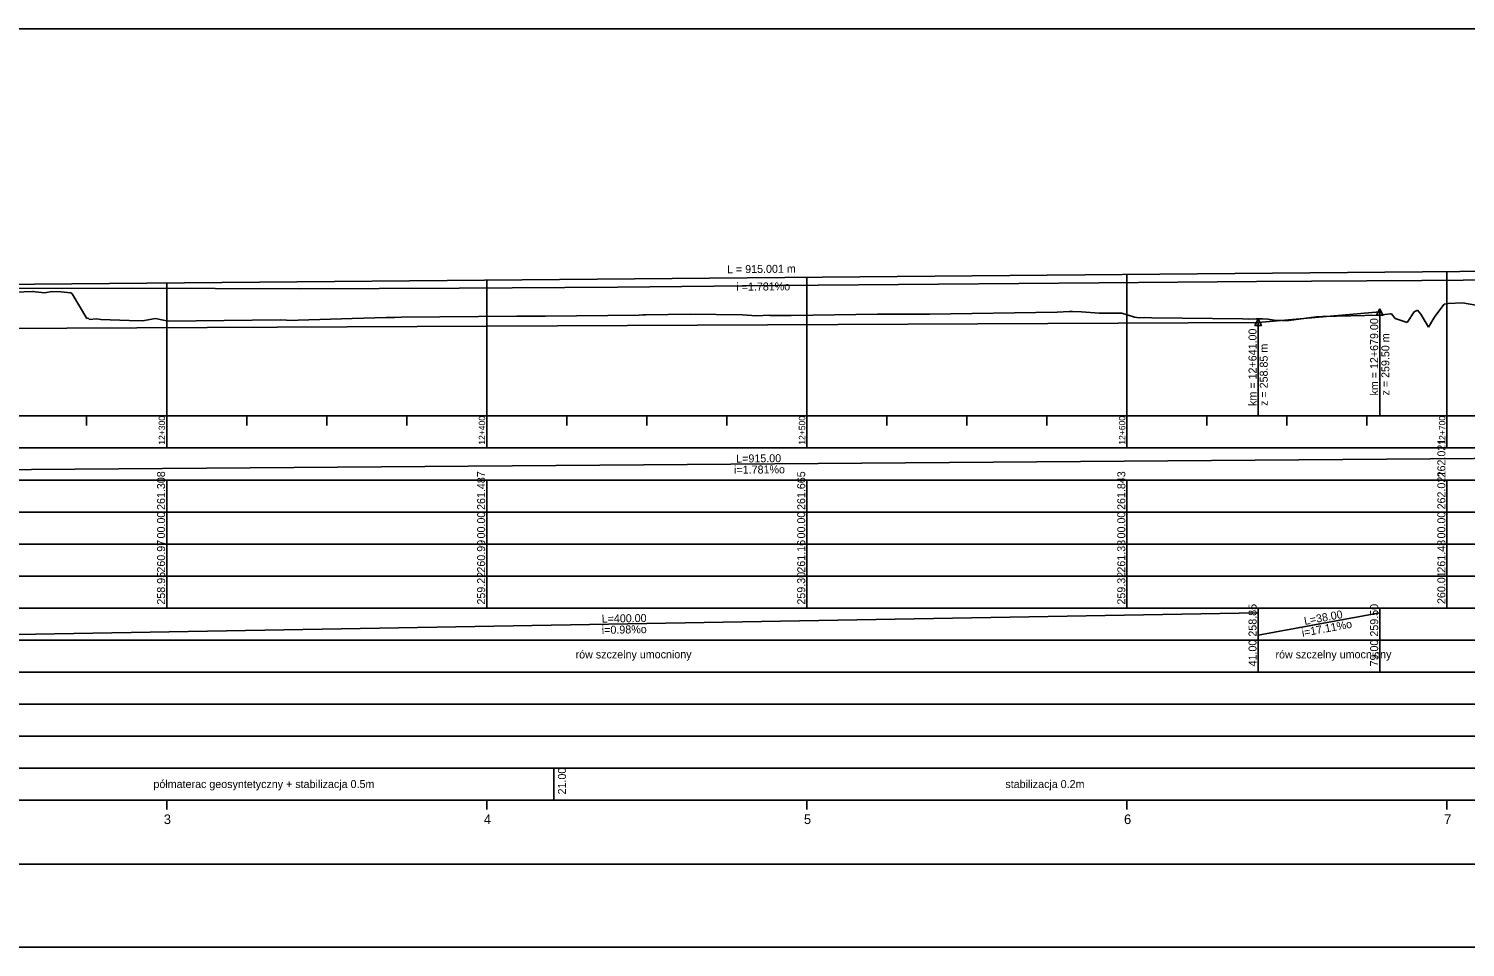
# Model space of a CAD drawing. Extents: x 6445630 to 6518227, y 5499240 to 5511716.
# Drawn here: x 6456888.1 to 6457336.9, y 5506751.3 to 5507038.3 of the extents above; entities that cross this region are included whole.
import ezdxf

# ---------------------------------------------------------------- set-up
doc = ezdxf.new("R2010")
doc.units = 0
for name, color, linetype in [('TOR_PROF-opisy pomocnicze', 7, 'Continuous'), ('TOR_PROF-rowy otwarte', 7, 'Continuous'), ('TOR_PROF-tabelka-geometria T1', 7, 'Continuous'), ('TOR_PROF-tabelka-kilometracja', 7, 'Continuous'), ('TOR_PROF-tabelka-odleglosci T1', 7, 'Continuous'), ('TOR_PROF-tabelka-pochylenia proj T1', 7, 'Continuous'), ('TOR_PROF-tabelka-rodzaj rowu T1', 7, 'Continuous'), ('TOR_PROF-tabelka-rowyT1', 7, 'Continuous'), ('TOR_PROF-tabelka-rurociagi T1', 7, 'Continuous'), ('TOR_PROF-tabelka-rzedne istn T1', 7, 'Continuous'), ('TOR_PROF-tabelka-rzedne proj T1', 7, 'Continuous'), ('TOR_PROF-tabelka-teren istniejacy T1', 7, 'Continuous'), ('TOR_PROF-tabelka-warstwa ochronna T1', 7, 'Continuous'), ('TOR_PROF-tor istniejacy T2', 7, 'Continuous'), ('TOR_PROF-tor projektowany', 7, 'Continuous'), ('TOR_PROF-uklad odniesienia', 7, 'Continuous'), ('TOR_PROF-warstwa ochronna', 7, 'Continuous'), ('TOR_RAMKI-dodatkowe3', 7, 'Continuous'), ('TOR_RAMKI-MASKA WYCIECIA', 7, 'Continuous')]:
    doc.layers.add(name, color=color, linetype=linetype)

msp = doc.modelspace()

# ---------------------------------------------------------------- linework, layer by layer
at = {"layer": 'TOR_PROF-opisy pomocnicze'}
for p, q in [((6457310.21, 5506949.8), (6457310.21, 5506922.8)), ((6457272.21, 5506946.55), (6457272.21, 5506919.55))]:
    msp.add_line(p, q, dxfattribs=at)
for points in [[(6457310.21, 5506950.8), (6457311.21, 5506948.8), (6457309.21, 5506948.8)], [(6457272.21, 5506947.55), (6457273.21, 5506945.55), (6457271.21, 5506945.55)]]:
    msp.add_lwpolyline(points, close=True, dxfattribs=at)
at = {"layer": 'TOR_PROF-rowy otwarte'}
for p, q in [((6457272.21, 5506946.55), (6457310.21, 5506949.8)), ((6456872.21, 5506944.6), (6457272.21, 5506946.55))]:
    msp.add_line(p, q, dxfattribs=at)
for points in [[(6457310.21, 5506949.8), (6457310.21, 5506922.3), (6457310.21, 5506917.3), (6457310.21, 5506917.3)], [(6457272.21, 5506946.55), (6457272.21, 5506922.3), (6457272.21, 5506917.3), (6457272.21, 5506917.3)]]:
    msp.add_lwpolyline(points, dxfattribs=at)
at = {"layer": 'TOR_PROF-tabelka-geometria T1'}
for points in [[(6452735.25, 5506777.3), (6458247.17, 5506777.3), (6458247.17, 5506779.97), (6458376.27, 5506779.97), (6458376.27, 5506777.3), (6458396.27, 5506777.3), (6458396.27, 5506774.64), (6458525.37, 5506774.64), (6458525.37, 5506777.3), (6458723.83, 5506777.3), (6458723.83, 5506777.3), (6458758.83, 5506774.64), (6458758.83, 5506774.64), (6458827.61, 5506774.64), (6458827.61, 5506774.64), (6458862.61, 5506777.3), (6458862.61, 5506777.3), (6458862.61, 5506777.3), (6458862.61, 5506777.3), (6458897.61, 5506779.97), (6458897.61, 5506779.97), (6458966.4, 5506779.97), (6458966.4, 5506779.97), (6459001.4, 5506777.3)], [(6452331.21, 5506777.3), (6459531.21, 5506777.3)]]:
    msp.add_lwpolyline(points, dxfattribs=at)
at = {"layer": 'TOR_PROF-tabelka-kilometracja'}
for points in [[(6456931.21, 5506794.3), (6456931.21, 5506797.3)], [(6457031.21, 5506794.3), (6457031.21, 5506797.3)], [(6457131.21, 5506794.3), (6457131.21, 5506797.3)], [(6457231.21, 5506794.3), (6457231.21, 5506797.3)], [(6457331.21, 5506794.3), (6457331.21, 5506797.3)]]:
    msp.add_lwpolyline(points, dxfattribs=at)
at = {"layer": 'TOR_PROF-tabelka-odleglosci T1'}
msp.add_lwpolyline([(6452331.21, 5506877.3), (6459531.21, 5506877.3), (6459531.21, 5506887.3), (6452331.21, 5506887.3)], close=True, dxfattribs=at)
for points in [[(6456931.21, 5506877.3), (6456931.21, 5506887.3)], [(6457031.21, 5506877.3), (6457031.21, 5506887.3)], [(6457131.21, 5506877.3), (6457131.21, 5506887.3)], [(6457231.21, 5506877.3), (6457231.21, 5506887.3)], [(6457331.21, 5506877.3), (6457331.21, 5506887.3)]]:
    msp.add_lwpolyline(points, dxfattribs=at)
at = {"layer": 'TOR_PROF-tabelka-pochylenia proj T1'}
msp.add_lwpolyline([(6452331.21, 5506897.3), (6459531.21, 5506897.3), (6459531.21, 5506907.3), (6452331.21, 5506907.3)], close=True, dxfattribs=at)
msp.add_lwpolyline([(6456656.74, 5506898.8), (6457571.74, 5506905.8)], dxfattribs=at)
at = {"layer": 'TOR_PROF-tabelka-rodzaj rowu T1'}
for points in [[(6452331.21, 5506837.3), (6459531.21, 5506837.3), (6459531.21, 5506847.3), (6452331.21, 5506847.3)], [(6452331.21, 5506817.3), (6459531.21, 5506817.3), (6459531.21, 5506827.3), (6452331.21, 5506827.3)]]:
    msp.add_lwpolyline(points, close=True, dxfattribs=at)
for points in [[(6457272.21, 5506837.3), (6457272.21, 5506847.3)], [(6457310.21, 5506837.3), (6457310.21, 5506847.3)]]:
    msp.add_lwpolyline(points, dxfattribs=at)
at = {"layer": 'TOR_PROF-tabelka-rowyT1'}
msp.add_lwpolyline([(6452331.21, 5506847.3), (6459531.21, 5506847.3), (6459531.21, 5506857.3), (6452331.21, 5506857.3)], close=True, dxfattribs=at)
for points in [[(6456872.21, 5506848.8), (6457272.21, 5506855.8)], [(6457272.21, 5506847.3), (6457272.21, 5506857.3)], [(6457272.21, 5506848.8), (6457310.21, 5506855.8)], [(6457310.21, 5506847.3), (6457310.21, 5506857.3)]]:
    msp.add_lwpolyline(points, dxfattribs=at)
at = {"layer": 'TOR_PROF-tabelka-rurociagi T1'}
msp.add_lwpolyline([(6452331.21, 5506827.3), (6459531.21, 5506827.3), (6459531.21, 5506837.3), (6452331.21, 5506837.3)], close=True, dxfattribs=at)
at = {"layer": 'TOR_PROF-tabelka-rzedne istn T1'}
msp.add_lwpolyline([(6452331.21, 5506867.3), (6459531.21, 5506867.3), (6459531.21, 5506877.3), (6452331.21, 5506877.3)], close=True, dxfattribs=at)
for points in [[(6456931.21, 5506867.3), (6456931.21, 5506877.3)], [(6457031.21, 5506867.3), (6457031.21, 5506877.3)], [(6457131.21, 5506867.3), (6457131.21, 5506877.3)], [(6457231.21, 5506867.3), (6457231.21, 5506877.3)], [(6457331.21, 5506867.3), (6457331.21, 5506877.3)], [(6456931.21, 5506857.3), (6456931.21, 5506867.3)], [(6456931.21, 5506857.3), (6456931.21, 5506867.3)], [(6456931.21, 5506857.3), (6456931.21, 5506867.3)], [(6457031.21, 5506857.3), (6457031.21, 5506867.3)], [(6457031.21, 5506857.3), (6457031.21, 5506867.3)], [(6457031.21, 5506857.3), (6457031.21, 5506867.3)], [(6457131.21, 5506857.3), (6457131.21, 5506867.3)], [(6457131.21, 5506857.3), (6457131.21, 5506867.3)], [(6457131.21, 5506857.3), (6457131.21, 5506867.3)], [(6457231.21, 5506857.3), (6457231.21, 5506867.3)], [(6457231.21, 5506857.3), (6457231.21, 5506867.3)], [(6457231.21, 5506857.3), (6457231.21, 5506867.3)], [(6457331.21, 5506857.3), (6457331.21, 5506867.3)], [(6457331.21, 5506857.3), (6457331.21, 5506867.3)], [(6457331.21, 5506857.3), (6457331.21, 5506867.3)]]:
    msp.add_lwpolyline(points, dxfattribs=at)
at = {"layer": 'TOR_PROF-tabelka-rzedne proj T1'}
msp.add_lwpolyline([(6452331.21, 5506887.3), (6459531.21, 5506887.3), (6459531.21, 5506897.3), (6452331.21, 5506897.3)], close=True, dxfattribs=at)
for points in [[(6456931.21, 5506887.3), (6456931.21, 5506897.3)], [(6457031.21, 5506887.3), (6457031.21, 5506897.3)], [(6457131.21, 5506887.3), (6457131.21, 5506897.3)], [(6457231.21, 5506887.3), (6457231.21, 5506897.3)], [(6457331.21, 5506887.3), (6457331.21, 5506897.3)]]:
    msp.add_lwpolyline(points, dxfattribs=at)
at = {"layer": 'TOR_PROF-tabelka-teren istniejacy T1'}
msp.add_lwpolyline([(6452331.21, 5506857.3), (6459531.21, 5506857.3), (6459531.21, 5506867.3), (6452331.21, 5506867.3)], close=True, dxfattribs=at)
msp.add_lwpolyline([(6452331.21, 5506857.3), (6459531.21, 5506857.3), (6459531.21, 5506867.3), (6452331.21, 5506867.3)], close=True, dxfattribs=at)
msp.add_lwpolyline([(6452331.21, 5506857.3), (6459531.21, 5506857.3), (6459531.21, 5506867.3), (6452331.21, 5506867.3)], close=True, dxfattribs=at)
at = {"layer": 'TOR_PROF-tabelka-warstwa ochronna T1'}
msp.add_lwpolyline([(6452331.21, 5506807.3), (6459531.21, 5506807.3), (6459531.21, 5506817.3), (6452331.21, 5506817.3)], close=True, dxfattribs=at)
at = {"layer": 'TOR_PROF-tor istniejacy T2'}
msp.add_lwpolyline([(6456273.83, 5506953.65), (6456323.85, 5506953.85), (6456373.37, 5506953.9), (6456420.81, 5506954.3), (6456470.2, 5506954.8), (6456521.75, 5506955.4), (6456572.89, 5506955.4), (6456623.47, 5506955.35), (6456672.67, 5506955.3), (6456723.03, 5506955.55), (6456772.56, 5506955.75), (6456819.97, 5506956.35), (6456866.68, 5506957.1), (6456920.08, 5506957.2), (6456972.6, 5506957.05), (6457022.59, 5506957.2), (6457072.2, 5506957.55), (6457122.23, 5506958.05), (6457172.36, 5506958.45), (6457222.5, 5506958.9), (6457271.74, 5506959.3), (6457323.35, 5506959.65), (6457375.16, 5506960.05)], dxfattribs=at)
at = {"layer": 'TOR_PROF-tor projektowany'}
msp.add_line((6456656.74, 5506956.4), (6457571.74, 5506964.55), dxfattribs=at)
msp.add_line((6456656.74, 5506956.4), (6457571.74, 5506964.55), dxfattribs=at)
for points in [[(6457231.21, 5506961.52), (6457231.21, 5506922.3), (6457231.21, 5506917.3), (6457231.21, 5506917.3)], [(6457231.21, 5506961.52), (6457231.21, 5506922.3), (6457231.21, 5506917.3), (6457231.21, 5506917.3)], [(6457331.21, 5506962.41), (6457331.21, 5506922.3), (6457331.21, 5506917.3), (6457331.21, 5506917.3)], [(6457331.21, 5506962.41), (6457331.21, 5506922.3), (6457331.21, 5506917.3), (6457331.21, 5506917.3)], [(6457331.21, 5506962.41), (6457331.21, 5506922.3), (6457331.21, 5506917.3), (6457331.21, 5506917.3)], [(6456931.21, 5506958.84), (6456931.21, 5506922.3), (6456931.21, 5506917.3), (6456931.21, 5506917.3)], [(6456931.21, 5506958.84), (6456931.21, 5506922.3), (6456931.21, 5506917.3), (6456931.21, 5506917.3)], [(6457031.21, 5506959.73), (6457031.21, 5506922.3), (6457031.21, 5506917.3), (6457031.21, 5506917.3)], [(6457031.21, 5506959.73), (6457031.21, 5506922.3), (6457031.21, 5506917.3), (6457031.21, 5506917.3)], [(6457131.21, 5506960.63), (6457131.21, 5506922.3), (6457131.21, 5506917.3), (6457131.21, 5506917.3)], [(6457131.21, 5506960.63), (6457131.21, 5506922.3), (6457131.21, 5506917.3), (6457131.21, 5506917.3)]]:
    msp.add_lwpolyline(points, dxfattribs=at)
at = {"layer": 'TOR_PROF-uklad odniesienia'}
for p, q in [((6452331.21, 5506917.3), (6459531.21, 5506917.3)), ((6456906.21, 5506914.3), (6456906.21, 5506917.3)), ((6456931.21, 5506907.3), (6456931.21, 5506917.3)), ((6456956.21, 5506914.3), (6456956.21, 5506917.3)), ((6456981.21, 5506914.3), (6456981.21, 5506917.3)), ((6457006.21, 5506914.3), (6457006.21, 5506917.3)), ((6457031.21, 5506907.3), (6457031.21, 5506917.3)), ((6457056.21, 5506914.3), (6457056.21, 5506917.3)), ((6457081.21, 5506914.3), (6457081.21, 5506917.3)), ((6457106.21, 5506914.3), (6457106.21, 5506917.3)), ((6457131.21, 5506907.3), (6457131.21, 5506917.3)), ((6457156.21, 5506914.3), (6457156.21, 5506917.3)), ((6457181.21, 5506914.3), (6457181.21, 5506917.3)), ((6457206.21, 5506914.3), (6457206.21, 5506917.3)), ((6457231.21, 5506907.3), (6457231.21, 5506917.3)), ((6457256.21, 5506914.3), (6457256.21, 5506917.3)), ((6457281.21, 5506914.3), (6457281.21, 5506917.3)), ((6457306.21, 5506914.3), (6457306.21, 5506917.3)), ((6457331.21, 5506907.3), (6457331.21, 5506917.3))]:
    msp.add_line(p, q, dxfattribs=at)
at = {"layer": 'TOR_PROF-warstwa ochronna'}
msp.add_lwpolyline([(6452331.21, 5506797.3), (6459531.21, 5506797.3), (6459531.21, 5506807.3), (6452331.21, 5506807.3)], close=True, dxfattribs=at)
msp.add_lwpolyline([(6457052.21, 5506797.3), (6457052.21, 5506807.3)], dxfattribs=at)
at = {"layer": 'TOR_RAMKI-dodatkowe3'}
for p, q in [((6456883.88, 5506955.98), (6456889.36, 5506956.17)), ((6456889.36, 5506956.17), (6456889.6, 5506956.18)), ((6456889.6, 5506956.18), (6456890.11, 5506956.06)), ((6456890.11, 5506956.06), (6456893.16, 5506955.74)), ((6456893.16, 5506955.74), (6456895.3, 5506956.17)), ((6456895.3, 5506956.17), (6456898.13, 5506956.06)), ((6456898.13, 5506956.06), (6456898.17, 5506956.05)), ((6456898.17, 5506956.05), (6456901.27, 5506955.83)), ((6456901.27, 5506955.83), (6456901.69, 5506955.45)), ((6456901.69, 5506955.45), (6456906.23, 5506947.79)), ((6457331.57, 5506952.43), (6457336.11, 5506952.67)), ((6457336.11, 5506952.67), (6457345.02, 5506951.11)), ((6456989.16, 5506947.74), (6456999.79, 5506948.08)), ((6456999.79, 5506948.08), (6457000.7, 5506948.1)), ((6457000.7, 5506948.1), (6457001.64, 5506948.09)), ((6457001.64, 5506948.09), (6457002.4, 5506948.12)), ((6457002.4, 5506948.12), (6457004.59, 5506948.18)), ((6457004.59, 5506948.18), (6457040.61, 5506948.45)), ((6457040.61, 5506948.45), (6457041.33, 5506948.45)), ((6457041.33, 5506948.45), (6457042.23, 5506948.44)), ((6457042.23, 5506948.44), (6457043.71, 5506948.44)), ((6457043.71, 5506948.44), (6457049.47, 5506948.5)), ((6457049.47, 5506948.5), (6457078.86, 5506948.82)), ((6457078.86, 5506948.82), (6457080, 5506948.87)), ((6457080, 5506948.87), (6457080.97, 5506948.87)), ((6457080.97, 5506948.87), (6457094.72, 5506949.08)), ((6457094.72, 5506949.08), (6457111.12, 5506948.96)), ((6457111.12, 5506948.96), (6457115.49, 5506948.64)), ((6457115.49, 5506948.64), (6457119.51, 5506948.77)), ((6457119.51, 5506948.77), (6457119.68, 5506948.66)), ((6457119.68, 5506948.66), (6457126.27, 5506948.75)), ((6457126.27, 5506948.75), (6457153.34, 5506949.15)), ((6457153.34, 5506949.15), (6457156.83, 5506949.09)), ((6457156.83, 5506949.09), (6457157.99, 5506949.16)), ((6457157.99, 5506949.16), (6457169.51, 5506949.09)), ((6457169.51, 5506949.09), (6457209.39, 5506949.73)), ((6457209.39, 5506949.73), (6457213.24, 5506950)), ((6457213.24, 5506950), (6457214.22, 5506950)), ((6457214.22, 5506950), (6457217.05, 5506949.82)), ((6457217.05, 5506949.82), (6457222.54, 5506949.41)), ((6457222.54, 5506949.41), (6457224.52, 5506949.41)), ((6457224.52, 5506949.41), (6457229.65, 5506949.4)), ((6457229.65, 5506949.4), (6457233.59, 5506948.15)), ((6457233.59, 5506948.15), (6457235.02, 5506947.93)), ((6457235.02, 5506947.93), (6457236.59, 5506948.09)), ((6457236.59, 5506948.09), (6457239.02, 5506947.94)), ((6457281.75, 5506947.09), (6457290.37, 5506948.33)), ((6457290.37, 5506948.33), (6457292.28, 5506948.37)), ((6457292.28, 5506948.37), (6457310, 5506948.76)), ((6457310, 5506948.76), (6457313.52, 5506949.25)), ((6457313.52, 5506949.25), (6457313.85, 5506949.22)), ((6457313.85, 5506949.22), (6457315, 5506947.79)), ((6457318.78, 5506946.51), (6457320.97, 5506949.88)), ((6457320.97, 5506949.88), (6457320.98, 5506949.89)), ((6457320.98, 5506949.89), (6457321.98, 5506950.36)), ((6457321.98, 5506950.36), (6457323.05, 5506949.15)), ((6457323.05, 5506949.15), (6457325.47, 5506945.03)), ((6457325.47, 5506945.03), (6457327.44, 5506948.39)), ((6457327.44, 5506948.39), (6457330.33, 5506952.2)), ((6457330.33, 5506952.2), (6457331.57, 5506952.43)), ((6456906.23, 5506947.79), (6456906.73, 5506947.83)), ((6456906.73, 5506947.83), (6456907.08, 5506947.43)), ((6456907.08, 5506947.43), (6456909.31, 5506947.64)), ((6456909.31, 5506947.64), (6456910.63, 5506947.46)), ((6456910.63, 5506947.46), (6456919.47, 5506947.15)), ((6456919.47, 5506947.15), (6456923.64, 5506947.02)), ((6456923.64, 5506947.02), (6456927.71, 5506947.72)), ((6456927.71, 5506947.72), (6456931.69, 5506946.94)), ((6456931.69, 5506946.94), (6456966.62, 5506947.37)), ((6456966.62, 5506947.37), (6456968.67, 5506947.28)), ((6456968.67, 5506947.28), (6456971.07, 5506947.15)), ((6456971.07, 5506947.15), (6456972.31, 5506947.19)), ((6456972.31, 5506947.19), (6456989.16, 5506947.74)), ((6457239.02, 5506947.94), (6457267.38, 5506947.61)), ((6457267.38, 5506947.61), (6457269.2, 5506947.56)), ((6457269.2, 5506947.56), (6457271.6, 5506947.62)), ((6457271.6, 5506947.62), (6457273.61, 5506947.67)), ((6457273.61, 5506947.67), (6457275.28, 5506947.54)), ((6457275.28, 5506947.54), (6457277.21, 5506947.22)), ((6457277.21, 5506947.22), (6457279.7, 5506947.13)), ((6457279.7, 5506947.13), (6457281.75, 5506947.09)), ((6457315, 5506947.79), (6457318.78, 5506946.51))]:
    msp.add_line(p, q, dxfattribs=at)
at = {"layer": 'TOR_RAMKI-MASKA WYCIECIA'}
msp.add_lwpolyline([(6455538.23, 5506751.3), (6457588.23, 5506751.3), (6457588.23, 5507038.3), (6455538.23, 5507038.3)], close=True, dxfattribs=at)

# ---------------------------------------------------------------- texts
at = {"layer": 'TOR_PROF-opisy pomocnicze'}
for s, rotation, p in [('L = 915.001 m', 0.5102, (6457106.29, 5506961.9)), ('L = 915.001 m', 0.5102, (6457106.29, 5506961.9)), ('  i =1.781%o', 0.5102, (6457107.34, 5506956.41)), ('  i =1.781%o', 0.5102, (6457107.34, 5506956.41)), ('km = 12+641.00', 90, (6457271.71, 5506920.45)), ('km = 12+679.00', 90, (6457309.71, 5506923.7)), ('z = 258.85 m', 90, (6457275.21, 5506920.45)), ('z = 259.50 m', 90, (6457313.21, 5506923.7))]:
    msp.add_text(s, height=2.5, rotation=rotation, dxfattribs=at).set_placement(p)
at = {"layer": 'TOR_PROF-tabelka-kilometracja'}
for s, p in [('3', (6456930.32, 5506789.8)), ('4', (6457030.32, 5506789.8)), ('5', (6457130.31, 5506789.8)), ('6', (6457230.32, 5506789.8)), ('7', (6457330.32, 5506789.8))]:
    msp.add_text(s, height=3, dxfattribs=at).set_placement(p)
at = {"layer": 'TOR_PROF-tabelka-odleglosci T1'}
for p in [(6456930.71, 5506879.04), (6457030.71, 5506879.04), (6457130.71, 5506879.04), (6457230.71, 5506879.04), (6457330.71, 5506879.04)]:
    msp.add_text('00.00', height=2.5, rotation=90, dxfattribs=at).set_placement(p)
at = {"layer": 'TOR_PROF-tabelka-pochylenia proj T1'}
for s, rotation, p in [('262.021', 90, (6457330.71, 5506898.11)), ('L=915.00', 0.4383, (6457109.16, 5506902.76)), ('i=1.781%o', 0.4383, (6457108.49, 5506899.26))]:
    msp.add_text(s, height=2.5, rotation=rotation, dxfattribs=at).set_placement(p)
at = {"layer": 'TOR_PROF-tabelka-rodzaj rowu T1'}
for s, p in [('41.00', (6457271.71, 5506839.05)), ('79.00', (6457309.71, 5506839.05))]:
    msp.add_text(s, height=2.5, rotation=90, dxfattribs=at).set_placement(p)
at = {"layer": 'TOR_PROF-tabelka-rowyT1'}
for s, rotation, p in [('258.85', 90, (6457271.71, 5506848.36)), ('259.50', 90, (6457309.71, 5506848.37)), ('L=400.00', 1.0026, (6457067.13, 5506852.71)), ('L=38.00', 10.4375, (6457286.8, 5506852)), ('i=0.98%o', 1.0026, (6457067.17, 5506849.21)), ('i=17.11%o', 10.4375, (6457286.08, 5506848.31)), ('rów szczelny umocniony', 0.087, (6457058.97, 5506841.54)), ('rów szczelny umocniony', 0.087, (6457277.63, 5506841.54))]:
    msp.add_text(s, height=2.5, rotation=rotation, dxfattribs=at).set_placement(p)
at = {"layer": 'TOR_PROF-tabelka-rzedne istn T1'}
for s, p in [('260.97', (6456930.71, 5506868.37)), ('260.99', (6457030.71, 5506868.37)), ('261.16', (6457130.71, 5506868.36)), ('261.33', (6457230.71, 5506868.37)), ('261.48', (6457330.71, 5506868.36)), ('258.95', (6456930.71, 5506858.36)), ('259.22', (6457030.71, 5506858.38)), ('259.30', (6457130.71, 5506858.37)), ('259.32', (6457230.71, 5506858.38)), ('260.01', (6457330.71, 5506858.54))]:
    msp.add_text(s, height=2.5, rotation=90, dxfattribs=at).set_placement(p)
at = {"layer": 'TOR_PROF-tabelka-rzedne proj T1'}
for s, p in [('261.308', (6456930.71, 5506887.94)), ('261.487', (6457030.71, 5506887.94)), ('261.665', (6457130.71, 5506887.93)), ('261.843', (6457230.71, 5506887.94)), ('262.021', (6457330.71, 5506888.11))]:
    msp.add_text(s, height=2.5, rotation=90, dxfattribs=at).set_placement(p)
at = {"layer": 'TOR_PROF-uklad odniesienia'}
for s, p in [('12+300', (6456930.71, 5506908.32)), ('12+400', (6457030.71, 5506908.32)), ('12+500', (6457130.71, 5506908.32)), ('12+600', (6457230.71, 5506908.32)), ('12+700', (6457330.71, 5506908.32))]:
    msp.add_text(s, height=2, rotation=90, dxfattribs=at).set_placement(p)
at = {"layer": 'TOR_PROF-warstwa ochronna'}
msp.add_text('21.00', height=2.5, rotation=90, dxfattribs=at).set_placement((6457055.97, 5506799.05))
for s, p in [('półmaterac geosyntetyczny + stabilizacja 0.5m', (6456927.07, 5506801.05)), ('stabilizacja 0.2m', (6457193.24, 5506801.05))]:
    msp.add_text(s, height=2.5, dxfattribs=at).set_placement(p)

doc.saveas('drawing.dxf')
